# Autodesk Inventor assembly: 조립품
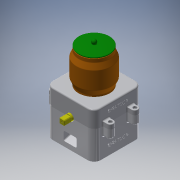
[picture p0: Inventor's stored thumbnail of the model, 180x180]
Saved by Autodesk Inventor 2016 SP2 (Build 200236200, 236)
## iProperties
Created: 2018-01
Part Number: 조립품
Document SubType Name: Assembly
Designer: Administrator
Author: Administrator
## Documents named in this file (6)
- D:\480107V1001\조립품.iam
- D:\480107V1001\본체.ipt
- D:\480107V1001\핸들축.ipt
- D:\480107V1001\본체커버.ipt
- D:\480107V1001\용기.ipt
- D:\480107V1001\용기캡.ipt
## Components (1 placed, 1 different names)
1. 핸들축:1
